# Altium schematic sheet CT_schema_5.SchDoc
size 314 x 170 mm
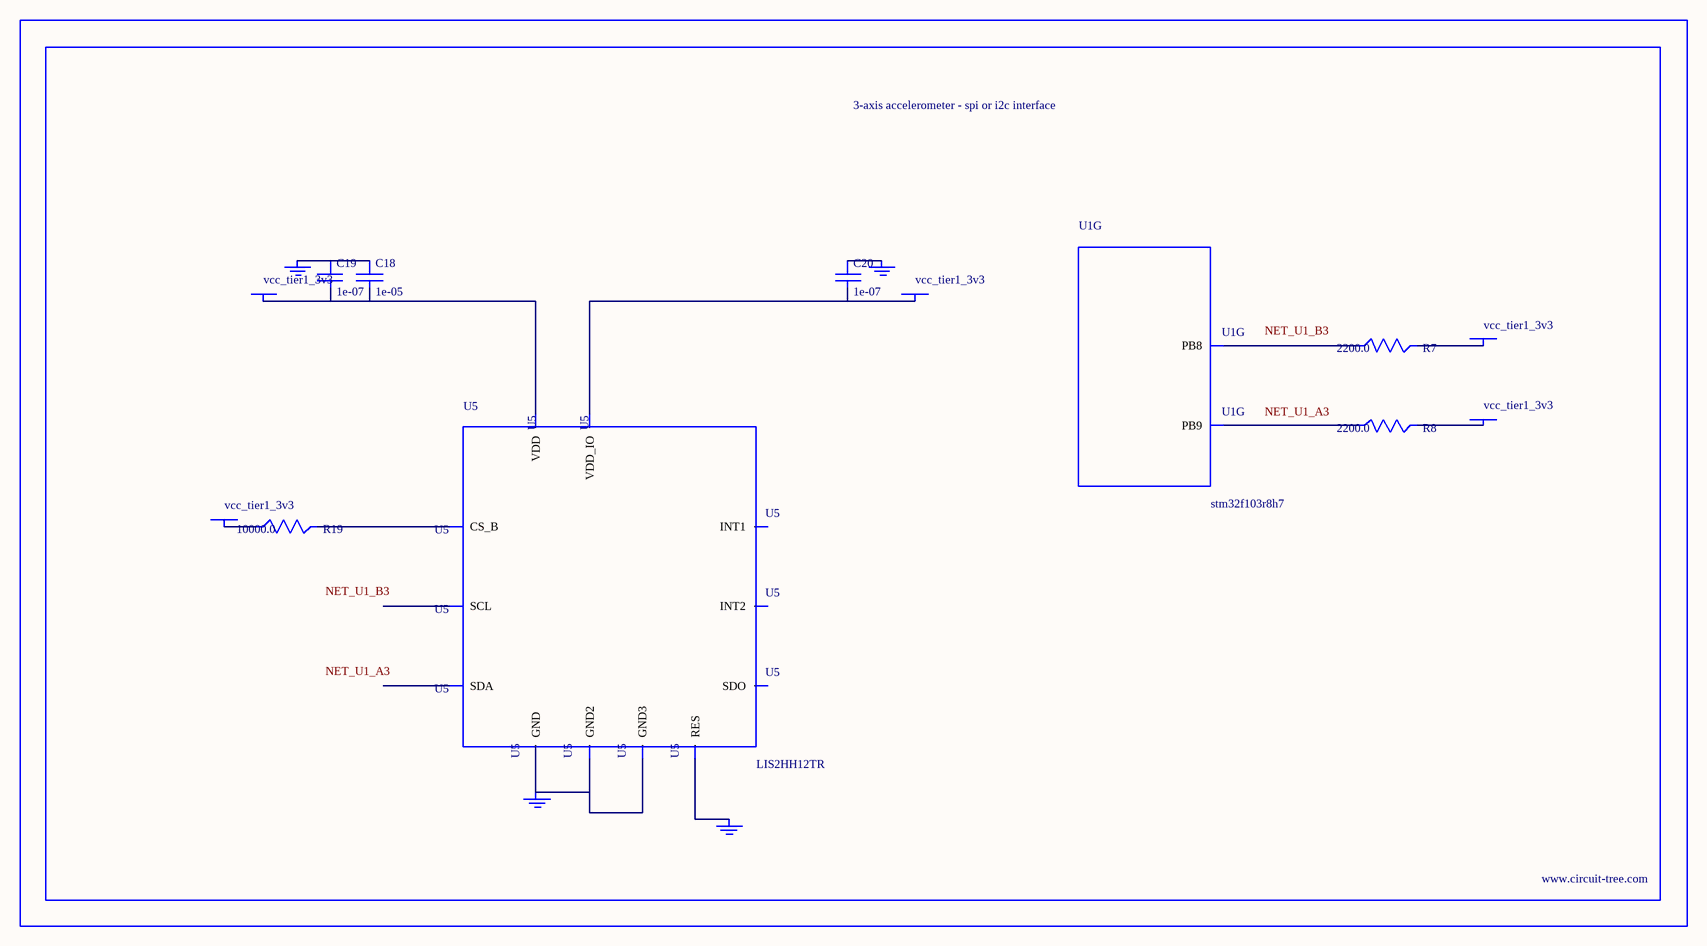
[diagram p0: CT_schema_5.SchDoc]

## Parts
BORDER4  (no value)
C18  1e-05  [C0805]
C19  1e-07  [C0402]
C20  1e-07  [C0402]
GND_INSTANCE_4_0  (no value)
GND_INSTANCE_4_1  (no value)
GND_INSTANCE_4_2  (no value)
GND_INSTANCE_4_3  (no value)
POWER_INSTANCE_4_0  vcc_tier1_3v3
POWER_INSTANCE_4_1  vcc_tier1_3v3
POWER_INSTANCE_4_2  vcc_tier1_3v3
POWER_INSTANCE_4_3  vcc_tier1_3v3
POWER_INSTANCE_4_4  vcc_tier1_3v3
R7  2200.0  [R0603]
R8  2200.0  [R0603]
R19  10000.0  [R0603]
U1  stm32f103r8h7  [TFBGA64]  (part G of 7)
U5  LIS2HH12TR  [LGA-12]

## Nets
NetC18_1: C18.1 C19.1 GND_INSTANCE_4_1.0(GND)
NetC18_2: C18.2 C19.2 POWER_INSTANCE_4_1.0(PWR) U5.9(VDD)
NetC20_1: C20.1 GND_INSTANCE_4_2.0(GND)
NetC20_2: C20.2 POWER_INSTANCE_4_2.0(PWR) U5.10(VDD_IO)
NetGND_INSTANCE_4_0_0: GND_INSTANCE_4_0.0(GND) U5.5(RES)
NetGND_INSTANCE_4_3_0: GND_INSTANCE_4_3.0(GND) U5.6(GND) U5.7(GND2) U5.8(GND3)
NetPOWER_INSTANCE_4_0_0: POWER_INSTANCE_4_0.0(PWR) R19.1
NetPOWER_INSTANCE_4_3_0: POWER_INSTANCE_4_3.0(PWR) R7.2
NetPOWER_INSTANCE_4_4_0: POWER_INSTANCE_4_4.0(PWR) R8.2
NetR7_1: R7.1 U1.B3(PB8)
NetR8_1: R8.1 U1.A3(PB9)
NetR19_2: R19.2 U5.2(CS_B)

Not connected (* = marked no-connect by the designer): U5 1(SCL) 3(SDO) 4(SDA) 11(INT2) 12(INT1)

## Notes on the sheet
- Labels drawn without touching a wire or pin: NET_U1_A3, NET_U1_B3

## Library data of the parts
BORDER4 = BORDER_PAGE4
C18 = C0805C106K8RACTU
C19 C20 = C0402C104K3RACTU
GND_INSTANCE_4_0-GND_INSTANCE_4_3 = GND
POWER_INSTANCE_4_0-POWER_INSTANCE_4_4 = PWR
R7 R8 = RC0603JR-072K2L
R19 = RC0603JR-0710KL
